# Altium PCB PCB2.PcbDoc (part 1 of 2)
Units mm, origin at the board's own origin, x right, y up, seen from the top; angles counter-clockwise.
Board outline 165.1 x 160.02 mm, 2 copper layers (Top Layer, Bottom Layer); 328 components, 756 nets, 2625 pads, 0 vias.
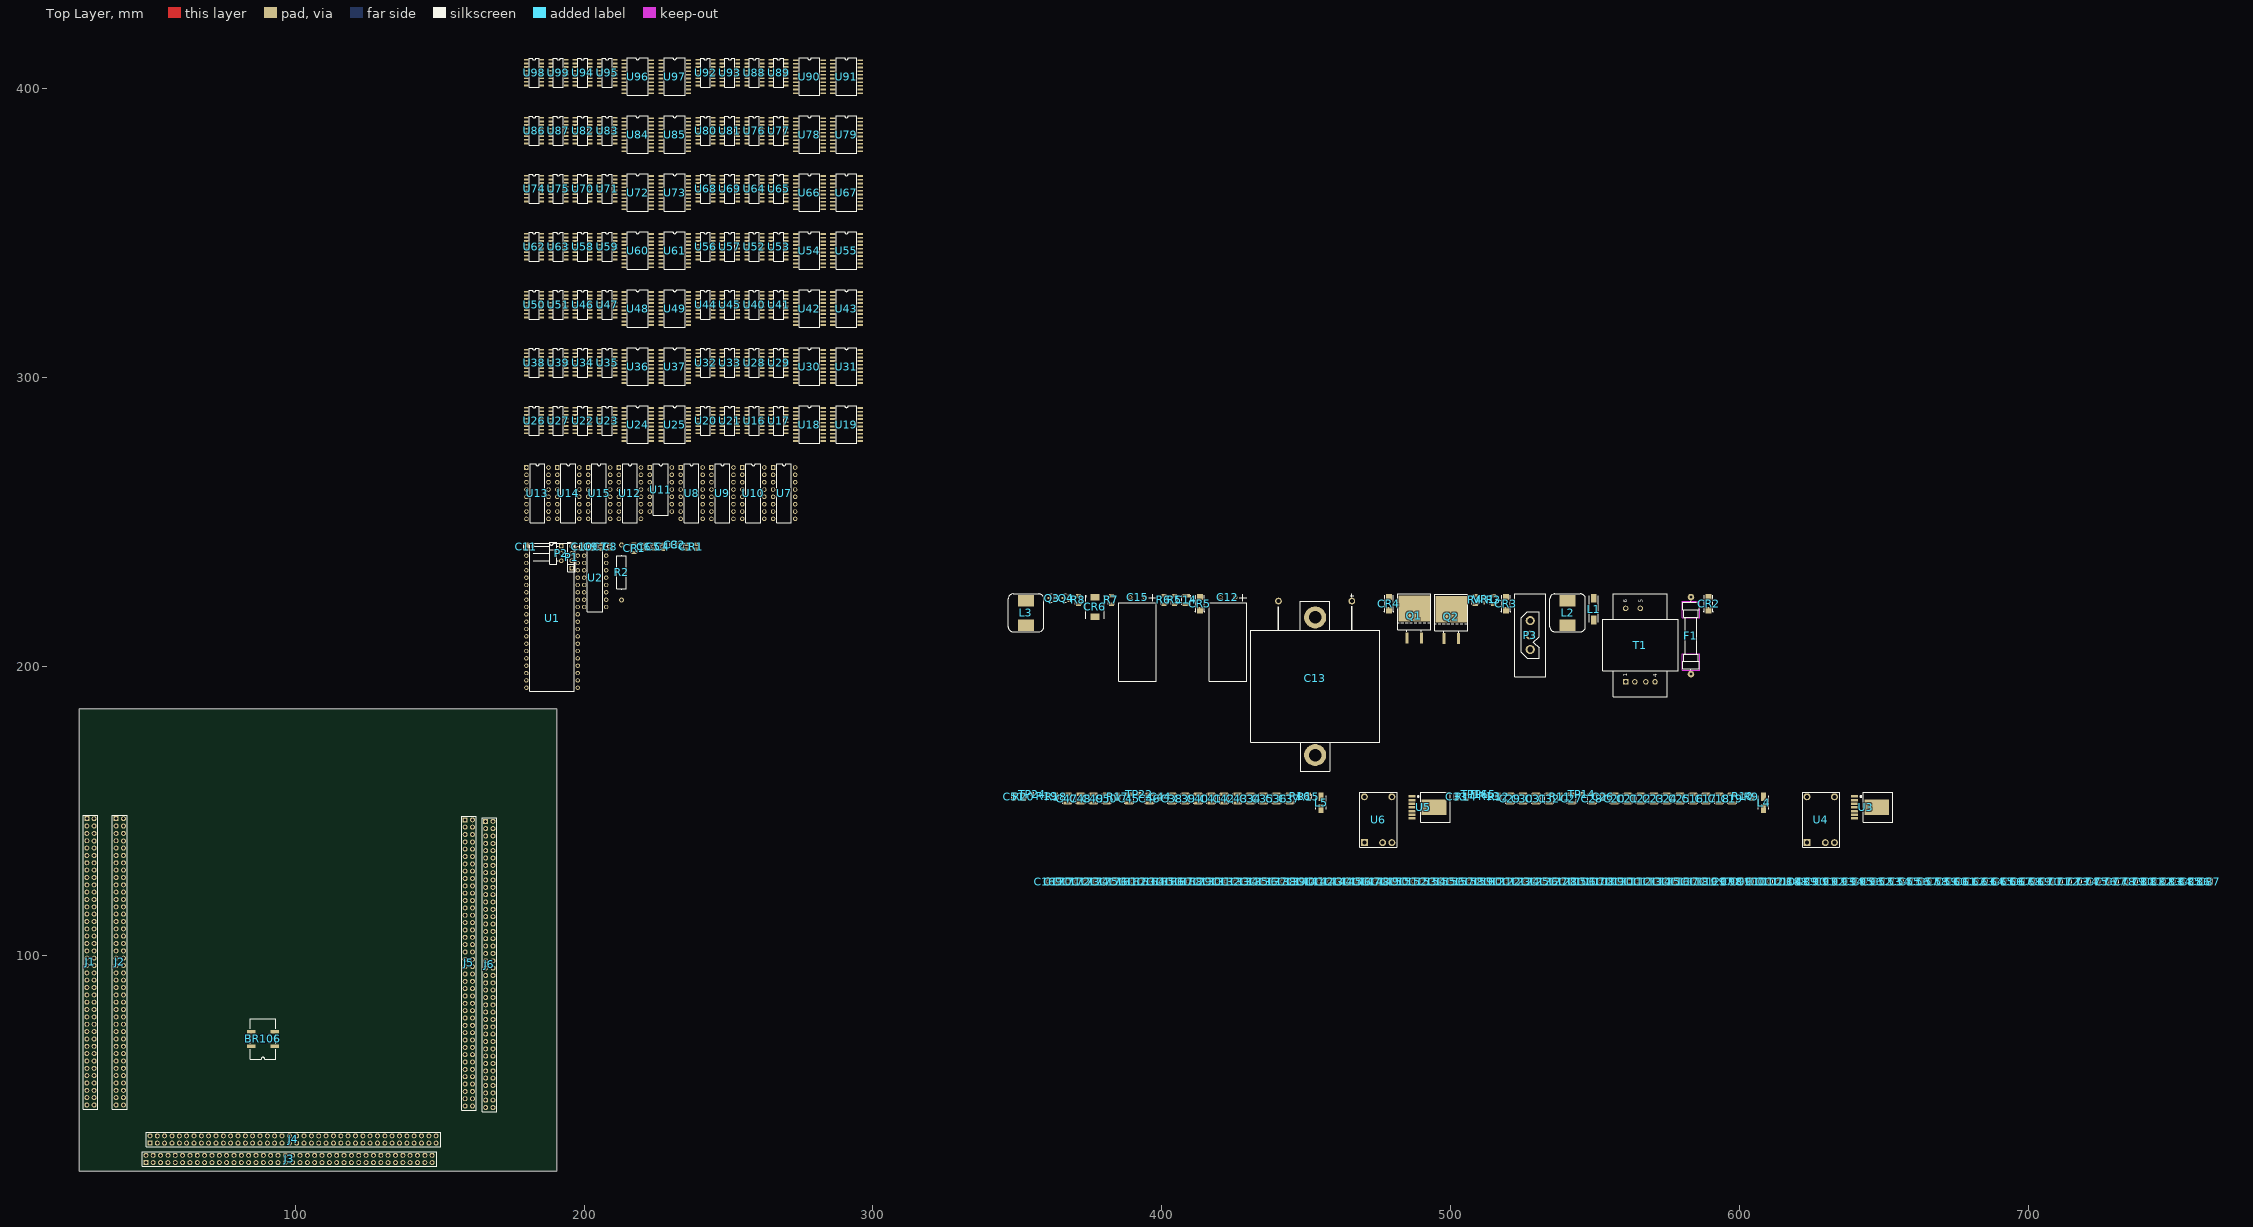
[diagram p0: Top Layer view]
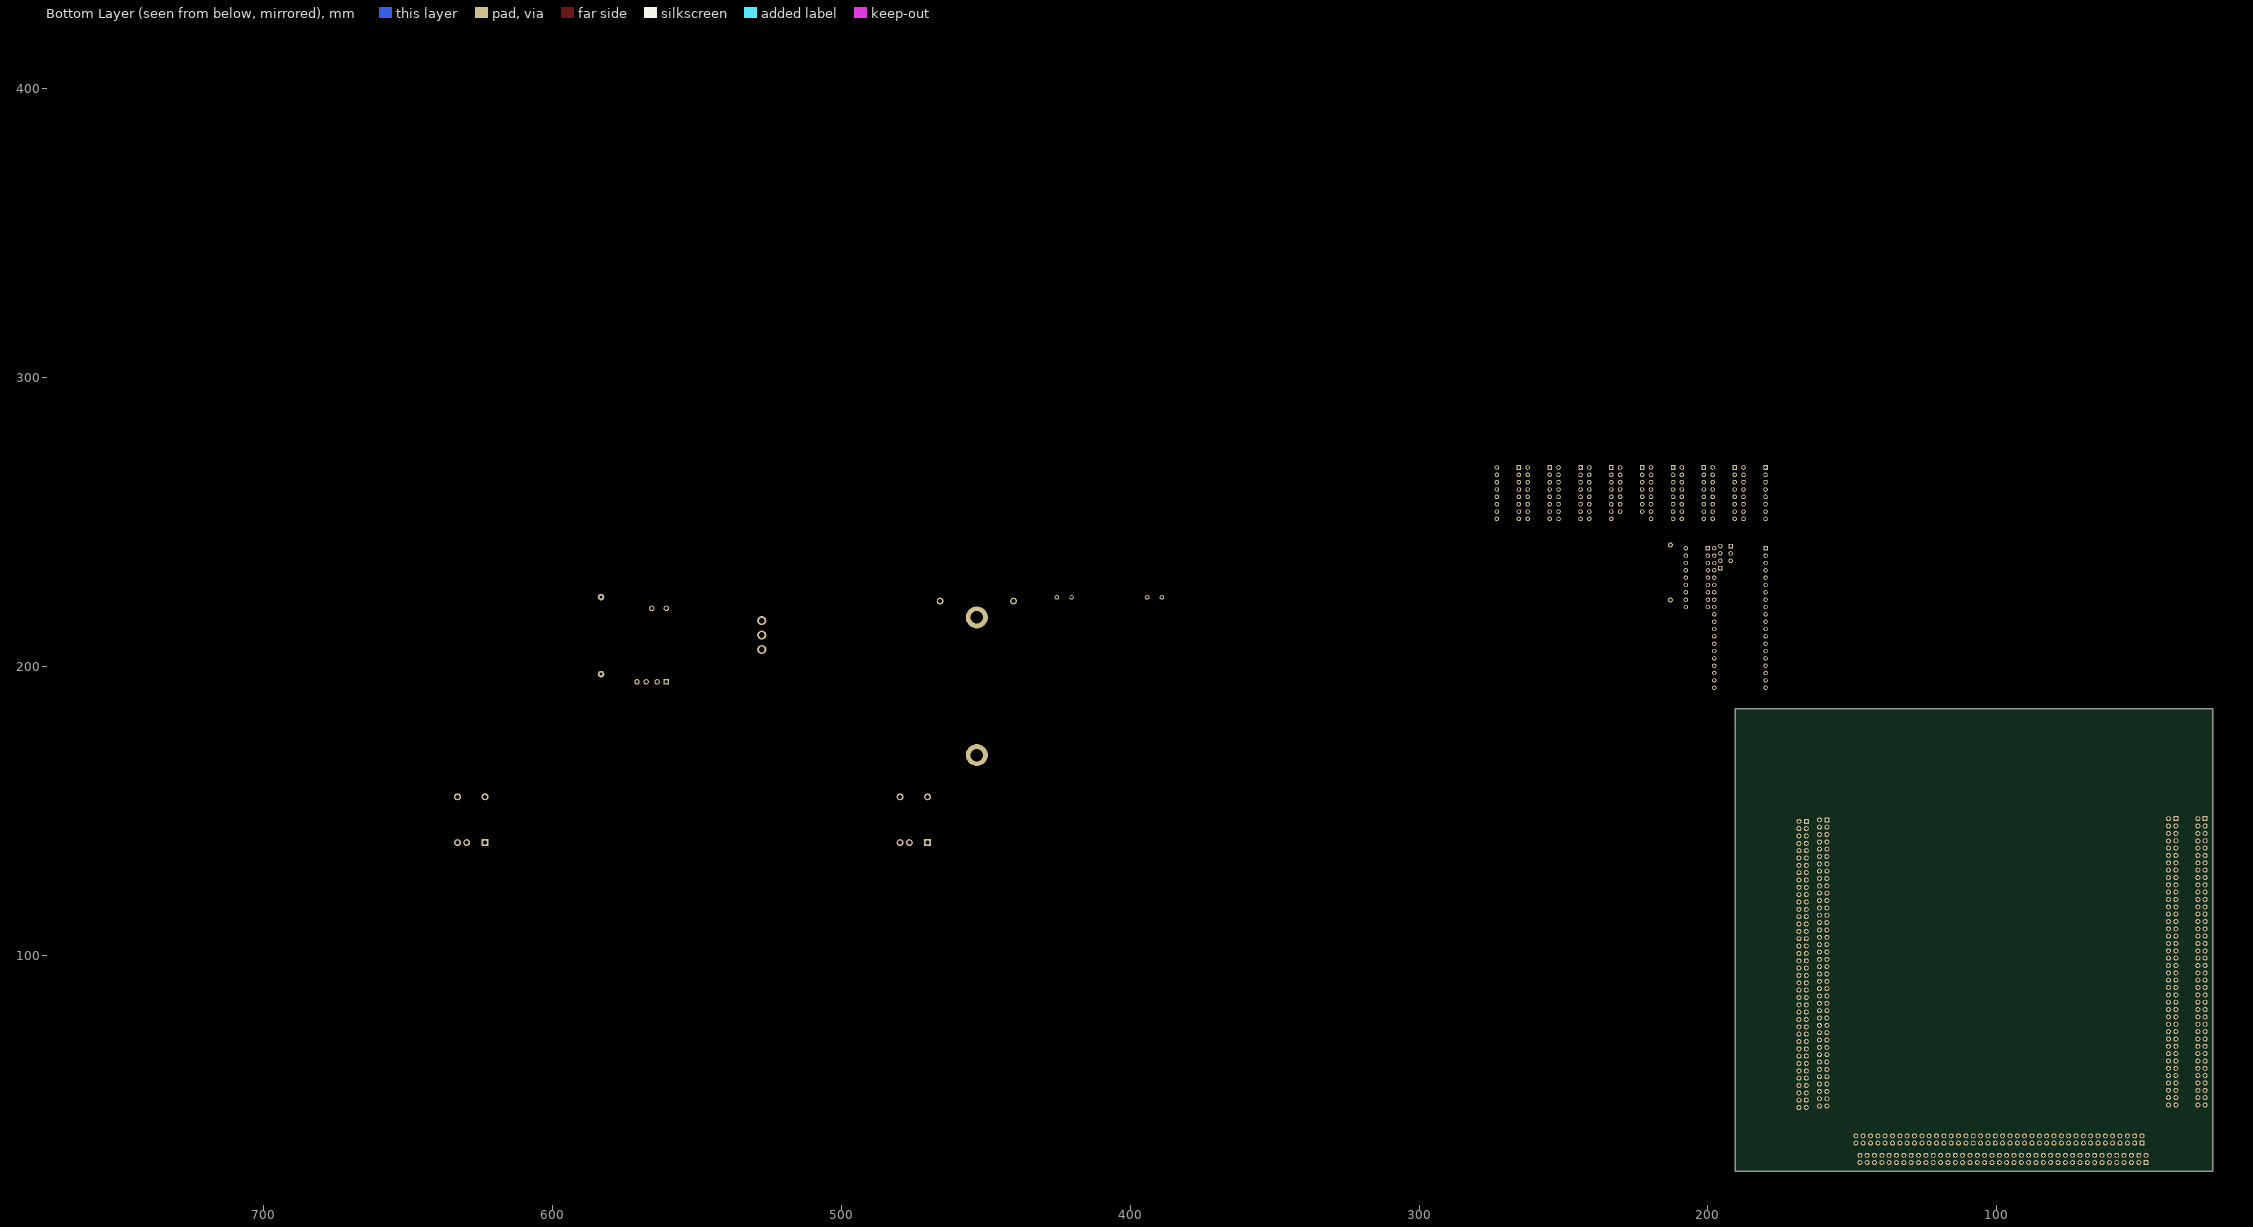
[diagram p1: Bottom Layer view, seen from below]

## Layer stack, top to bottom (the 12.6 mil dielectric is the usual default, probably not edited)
Top Layer: signal copper 0.0356
Dielectric: dielectric 0.32, FR-4, Dk 4.8
Bottom Layer: signal copper 0.0356

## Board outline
25.4,25.4 25.4,185.42 190.5,185.42 190.5,25.4

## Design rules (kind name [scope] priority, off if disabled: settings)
Clearance [All] p1: gap=0.254
PolygonConnect [All] p1: connectstyle=Relief reliefconductorwidth=0.254 reliefentries=4 polygonreliefangle="90 Angle" airgapwidth=0.254
RoomDefinition Latch7 [InComponentClass('Latch7')] p1: confinementstyle=ConfineIn formatcopy=TRUE lockcomponents=FALSE outline 178.943,397.383 296.799,397.383 296.799,410.845 178.943,410.845
RoomDefinition Latch6 [InComponentClass('Latch6')] p2: confinementstyle=ConfineIn formatcopy=TRUE lockcomponents=FALSE outline 178.943,377.317 296.799,377.317 296.799,390.779 178.943,390.779
RoomDefinition Latch5 [InComponentClass('Latch5')] p3: confinementstyle=ConfineIn formatcopy=TRUE lockcomponents=FALSE outline 178.943,357.251 296.799,357.251 296.799,370.713 178.943,370.713
RoomDefinition Latch4 [InComponentClass('Latch4')] p4: confinementstyle=ConfineIn formatcopy=TRUE lockcomponents=FALSE outline 178.943,337.185 296.799,337.185 296.799,350.647 178.943,350.647
RoomDefinition Latch3 [InComponentClass('Latch3')] p5: confinementstyle=ConfineIn formatcopy=TRUE lockcomponents=FALSE outline 178.943,317.119 296.799,317.119 296.799,330.581 178.943,330.581
RoomDefinition Latch2 [InComponentClass('Latch2')] p6: confinementstyle=ConfineIn formatcopy=TRUE lockcomponents=FALSE outline 178.943,297.053 296.799,297.053 296.799,310.515 178.943,310.515
RoomDefinition Latch1 [InComponentClass('Latch1')] p7: confinementstyle=ConfineIn formatcopy=TRUE lockcomponents=FALSE outline 178.943,276.987 296.799,276.987 296.799,290.449 178.943,290.449
RoomDefinition Decoder [InComponentClass('Decoder')] p8: confinementstyle=ConfineIn formatcopy=TRUE lockcomponents=FALSE outline 179.07,249.555 274.066,249.555 274.066,270.383 179.07,270.383
RoomDefinition Controller [InComponentClass('Controller')] p9: confinementstyle=ConfineIn formatcopy=TRUE lockcomponents=FALSE outline 178.943,221.869 239.903,221.869 239.903,243.205 178.943,243.205
RoomDefinition Connector [InComponentClass('Connector')] p10: confinementstyle=ConfineIn formatcopy=TRUE lockcomponents=FALSE outline 178.943,118.237 217.297,118.237 217.297,220.599 178.943,220.599
RoomDefinition ByPass [InComponentClass('ByPass')] p11: confinementstyle=ConfineIn formatcopy=TRUE lockcomponents=FALSE outline 359.664,123.814 763.778,123.814 763.778,127.37 359.664,127.37
RoomDefinition "28 PowerSupply" [InComponentClass('28 PowerSupply')] p12: confinementstyle=ConfineIn formatcopy=TRUE lockcomponents=FALSE outline 346.456,163.449 591.058,163.449 591.058,225.425 346.456,225.425
RoomDefinition "15 and 5 Volts" [InComponentClass('15 and 5 Volts')] p13: confinementstyle=ConfineIn formatcopy=TRUE lockcomponents=FALSE outline 347.726,137.263 653.161,137.263 653.161,156.694 347.726,156.694
RoutingVias [All] p1: holewidth=0.711 width=1.27 viastyle="Through Hole" minholewidth=0.711 minwidth=1.27 maxholewidth=0.711 maxwidth=1.27
SilkscreenOverComponentPads [All] p1: minsilkscreentomaskgap=0.254
SolderMaskExpansion [All] p1: expansion=0.102
Width [All] p1: maxlimit=0.254 minlimit=0.254 preferedwidth=0.254
27 further rules are at their usual default settings.

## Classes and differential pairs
net class Power1: NetCR2_1 NetCR4_2
net class D[0..7]: D0 D1 D2 D3 D4 D5 D6 D7
component class Latch7: U88 U89 U90 U91 U92 U93 U94 U95 U96 U97 U98 U99
component class Latch6: U76 U77 U78 U79 U80 U81 U82 U83 U84 U85 U86 U87
component class Latch5: U64 U65 U66 U67 U68 U69 U70 U71 U72 U73 U74 U75
component class Latch4: U52 U53 U54 U55 U56 U57 U58 U59 U60 U61 U62 U63
component class Latch3: U40 U41 U42 U43 U44 U45 U46 U47 U48 U49 U50 U51
component class Latch2: U28 U29 U30 U31 U32 U33 U34 U35 U36 U37 U38 U39
component class Latch1: U16 U17 U18 U19 U20 U21 U22 U23 U24 U25 U26 U27
component class Decoder: U7 U8 U9 U10 U11 U12 U13 U14 U15
component class Controller: C1 C2 C3 C4 C5 C6 C7 C8 C9 C10 C11 CR1 P1 P2 R1 R2 U1 U2 Y1
component class Connector: J1 J2 J3 J4 J5 J6
component class ByPass: C52 C53 C54 C55 C56 C57 C58 C59 C60 C61 C62 C63 C64 C65 C66 C67 C68 C69 C70 C71 C72 C73 C74 C75 C76 C77 C78 C79 C80 C81 C82 C83 C84 C85 C86 C87 C88 C89 C90 C91 C92 C93 C94 C95 C96 C97 C98 C99 C100 C101 C102 C103 C104 C105 C106 C107 C108 C109 C110 C111 C112 C113 C114 C115 C116 C117 C118 C119 C120 C121 C122 C123 C124 C125 C126 C127 C128 C129 C130 C131 C132 C133 C134 C135 C136 C137 C138 C139 C140 C141 C142 C143 C144 C145 C146 C147 C148 C149 C150 C151 C152 C153 C154 C155 C156 C157 C158 C159 C160 C161 C162 C163 C164 C165 C166 C167 C168 C169 C170 C171 C172 C173 C174 C175 C176
component class "28 PowerSupply": C12 C13 C14 C15 CR2 CR3 CR4 CR5 CR6 F1 L1 L2 L3 P3 Q1 Q2 Q3 Q4 R3 R4 R5 R6 R7 R8 T1 TP1 TP2 TP3 TP4 TP5 TP6 TP7 TP8 VR1 VR2 VR3
component class "15 and 5 Volts": C16 C17 C18 C19 C20 C21 C22 C23 C24 C25 C26 C27 C28 C29 C30 C31 C32 C33 C34 C35 C36 C37 C38 C39 C40 C41 C42 C43 C44 C45 C46 C47 C48 C49 C50 C51 L4 L5 R9 R10 R11 R12 R13 R14 R15 R16 R17 R18 R19 R20 TP14 TP15 TP16 TP22 TP24 U3 U4 U5 U6

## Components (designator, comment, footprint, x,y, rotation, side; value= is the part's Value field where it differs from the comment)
BR106 "Comment" XTAL1/N 88.9,71.12 r180 top
C1 "104-50V-10CX0805" 0805/1.3/N 235.458,241.427 r90 top
C2 "22P-25V-10NX0402" 0402/0.6/N 232.664,242.062 r90 top
C3 "22P-25V-10NX0402" 0402/0.6/N 230.124,242.062 r90 top
C4 "474-50V-10CX0805" 0805/1.4/N 227.33,241.427 r90 top
C5 "104-50V-10CX0805" 0805/1.3/N 224.155,241.427 r90 top
C6 "104-50V-10CX0805" 0805/1.3/N 220.853,241.427 r90 top
C7 "104-50V-10CX0805" 0805/1.3/N 205.867,241.427 r90 top
C8 "104-50V-10CX0805" 0805/1.3/N 209.042,241.427 r90 top
C9 "104-50V-10CX0805" 0805/1.3/N 202.565,241.427 r90 top
C10 "104-50V-10CX0805" 0805/1.3/N 199.39,241.427 r90 top
C11 "104-50V-10CX0805" 0805/1.3/N 180.086,241.427 r90 top
C12 "477-50V-20AV" RH+.2/.512/1 425.323,223.901 r0 top
C13 "MLPCAPSHORT" CAP_MLP222M063EK0A 440.309,222.631 r90 top
C14 "105-101-10CX1210" 1210/2.8/N 408.432,223.012 r90 top
C15 "477-50V-20AV" RH+.2/.512/1 394.081,223.901 r0 top
C16 "475-50V-10CX1210" 1210/2.8/N 583.819,154.281 r90 top
C17 "475-50V-10CX1210" 1210/2.8/N 588.264,154.281 r90 top
C18 "475-50V-10CX1210" 1210/2.8/N 592.836,154.281 r90 top
C19 "475-50V-10CX1210" 1210/2.8/N 597.281,154.281 r90 top
C20 "226-25V-10CX1210" 1210/2.8/N 556.641,154.281 r90 top
C21 "226-25V-10CX1210" 1210/2.8/N 561.213,154.281 r90 top
C22 "226-25V-10CX1210" 1210/2.8/N 565.658,154.281 r90 top
C23 "226-25V-10CX1210" 1210/2.8/N 570.23,154.281 r90 top
C24 "226-25V-10CX1210" 1210/2.8/N 574.675,154.281 r90 top
C25 "226-25V-10CX1210" 1210/2.8/N 579.247,154.281 r90 top
C26 "333-50V-10CX0805" 0805/1.3/N 552.704,154.916 r90 top
C27 "475-50V-10CX1210" 1210/2.8/N 541.782,154.281 r90 top
C28 "475-50V-10CX1210" 1210/2.8/N 548.894,154.281 r90 top
C29 "226-25V-10CX1210" 1210/2.8/N 520.446,154.281 r90 top
C30 "226-25V-10CX1210" 1210/2.8/N 524.891,154.281 r90 top
C31 "226-25V-10CX1210" 1210/2.8/N 529.463,154.281 r90 top
C32 "226-25V-10CX1210" 1210/2.8/N 534.035,154.281 r90 top
C33 "472-101-10CX0805" 0805/1.3/N 502.031,154.916 r90 top
C34 "475-50V-10CX1210" 1210/2.8/N 430.657,154.281 r90 top
C35 "475-50V-10CX1210" 1210/2.8/N 435.102,154.281 r90 top
C36 "475-50V-10CX1210" 1210/2.8/N 439.674,154.281 r90 top
C37 "475-50V-10CX1210" 1210/2.8/N 444.246,154.281 r90 top
C38 "226-25V-10CX1210" 1210/2.8/N 403.479,154.281 r90 top
C39 "226-25V-10CX1210" 1210/2.8/N 408.051,154.281 r90 top
C40 "226-25V-10CX1210" 1210/2.8/N 412.496,154.281 r90 top
C41 "226-25V-10CX1210" 1210/2.8/N 417.068,154.281 r90 top
C42 "226-25V-10CX1210" 1210/2.8/N 421.513,154.281 r90 top
C43 "226-25V-10CX1210" 1210/2.8/N 426.085,154.281 r90 top
C44 "333-50V-10CX0805" 0805/1.3/N 399.542,154.916 r90 top
C45 "475-50V-10CX1210" 1210/2.8/N 388.62,154.281 r90 top
C46 "475-50V-10CX1210" 1210/2.8/N 395.732,154.281 r90 top
C47 "226-25V-10CX1210" 1210/2.8/N 367.284,154.281 r90 top
C48 "226-25V-10CX1210" 1210/2.8/N 371.856,154.281 r90 top
C49 "226-25V-10CX1210" 1210/2.8/N 376.301,154.281 r90 top
C50 "226-25V-10CX1210" 1210/2.8/N 380.873,154.281 r90 top
C51 "472-101-10CX0805" 0805/1.3/N 348.869,154.916 r90 top
C52 "104-50V-10CX0805" 0805/1.3/N 649.224,125.592 r90 top
C53 "104-50V-10CX0805" 0805/1.3/N 652.399,125.592 r90 top
C54 "104-50V-10CX0805" 0805/1.3/N 655.701,125.592 r90 top
C55 "104-50V-10CX0805" 0805/1.3/N 658.876,125.592 r90 top
C56 "104-50V-10CX0805" 0805/1.3/N 662.178,125.592 r90 top
C57 "104-50V-10CX0805" 0805/1.3/N 665.353,125.592 r90 top
C58 "104-50V-10CX0805" 0805/1.3/N 668.655,125.592 r90 top
C59 "104-50V-10CX0805" 0805/1.3/N 671.83,125.592 r90 top
C60 "104-50V-10CX0805" 0805/1.3/N 675.132,125.592 r90 top
C61 "104-50V-10CX0805" 0805/1.3/N 678.307,125.592 r90 top
C62 "104-50V-10CX0805" 0805/1.3/N 681.609,125.592 r90 top
C63 "104-50V-10CX0805" 0805/1.3/N 684.784,125.592 r90 top
C64 "104-50V-10CX0805" 0805/1.3/N 688.086,125.592 r90 top
C65 "104-50V-10CX0805" 0805/1.3/N 691.261,125.592 r90 top
C66 "104-50V-10CX0805" 0805/1.3/N 694.563,125.592 r90 top
C67 "104-50V-10CX0805" 0805/1.3/N 697.738,125.592 r90 top
C68 "104-50V-10CX0805" 0805/1.3/N 701.04,125.592 r90 top
C69 "104-50V-10CX0805" 0805/1.3/N 704.342,125.592 r90 top
C70 "104-50V-10CX0805" 0805/1.3/N 707.517,125.592 r90 top
C71 "104-50V-10CX0805" 0805/1.3/N 710.819,125.592 r90 top
C72 "104-50V-10CX0805" 0805/1.3/N 713.994,125.592 r90 top
C73 "104-50V-10CX0805" 0805/1.3/N 717.296,125.592 r90 top
C74 "104-50V-10CX0805" 0805/1.3/N 720.471,125.592 r90 top
C75 "104-50V-10CX0805" 0805/1.3/N 723.773,125.592 r90 top
C76 "104-50V-10CX0805" 0805/1.3/N 726.948,125.592 r90 top
C77 "104-50V-10CX0805" 0805/1.3/N 730.25,125.592 r90 top
C78 "104-50V-10CX0805" 0805/1.3/N 733.425,125.592 r90 top
C79 "104-50V-10CX0805" 0805/1.3/N 736.727,125.592 r90 top
C80 "104-50V-10CX0805" 0805/1.3/N 739.902,125.592 r90 top
C81 "104-50V-10CX0805" 0805/1.3/N 743.204,125.592 r90 top
C82 "104-50V-10CX0805" 0805/1.3/N 746.379,125.592 r90 top
C83 "104-50V-10CX0805" 0805/1.3/N 749.681,125.592 r90 top
C84 "104-50V-10CX0805" 0805/1.3/N 752.856,125.592 r90 top
C85 "104-50V-10CX0805" 0805/1.3/N 756.158,125.592 r90 top
C86 "104-50V-10CX0805" 0805/1.3/N 759.333,125.592 r90 top
C87 "104-50V-10CX0805" 0805/1.3/N 762.635,125.592 r90 top
C88 "104-50V-10CX0805" 0805/1.3/N 620.014,125.592 r90 top
C89 "104-50V-10CX0805" 0805/1.3/N 623.316,125.592 r90 top
C90 "104-50V-10CX0805" 0805/1.3/N 626.491,125.592 r90 top
C91 "104-50V-10CX0805" 0805/1.3/N 629.793,125.592 r90 top
C92 "104-50V-10CX0805" 0805/1.3/N 632.968,125.592 r90 top
C93 "104-50V-10CX0805" 0805/1.3/N 636.27,125.592 r90 top
C94 "104-50V-10CX0805" 0805/1.3/N 639.445,125.592 r90 top
C95 "104-50V-10CX0805" 0805/1.3/N 642.747,125.592 r90 top
C96 "104-50V-10CX0805" 0805/1.3/N 645.922,125.592 r90 top
C97 "104-50V-10CX0805" 0805/1.3/N 594.106,125.592 r90 top
C98 "104-50V-10CX0805" 0805/1.3/N 597.408,125.592 r90 top
C99 "104-50V-10CX0805" 0805/1.3/N 600.583,125.592 r90 top
C100 "104-50V-10CX0805" 0805/1.3/N 603.885,125.592 r90 top
C101 "104-50V-10CX0805" 0805/1.3/N 607.06,125.592 r90 top
C102 "104-50V-10CX0805" 0805/1.3/N 610.362,125.592 r90 top
C103 "104-50V-10CX0805" 0805/1.3/N 613.537,125.592 r90 top
C104 "104-50V-10CX0805" 0805/1.3/N 616.839,125.592 r90 top
C105 "104-50V-10CX0805" 0805/1.3/N 542.29,125.592 r90 top
C106 "104-50V-10CX0805" 0805/1.3/N 545.465,125.592 r90 top
C107 "104-50V-10CX0805" 0805/1.3/N 548.767,125.592 r90 top
C108 "104-50V-10CX0805" 0805/1.3/N 551.942,125.592 r90 top
C109 "104-50V-10CX0805" 0805/1.3/N 555.244,125.592 r90 top
C110 "104-50V-10CX0805" 0805/1.3/N 558.419,125.592 r90 top
C111 "104-50V-10CX0805" 0805/1.3/N 561.721,125.592 r90 top
C112 "104-50V-10CX0805" 0805/1.3/N 564.896,125.592 r90 top
C113 "104-50V-10CX0805" 0805/1.3/N 568.198,125.592 r90 top
C114 "104-50V-10CX0805" 0805/1.3/N 571.5,125.592 r90 top
C115 "104-50V-10CX0805" 0805/1.3/N 574.675,125.592 r90 top
C116 "104-50V-10CX0805" 0805/1.3/N 577.977,125.592 r90 top
C117 "104-50V-10CX0805" 0805/1.3/N 581.152,125.592 r90 top
C118 "104-50V-10CX0805" 0805/1.3/N 584.454,125.592 r90 top
C119 "104-50V-10CX0805" 0805/1.3/N 587.629,125.592 r90 top
C120 "104-50V-10CX0805" 0805/1.3/N 590.931,125.592 r90 top
C121 "104-50V-10CX0805" 0805/1.3/N 516.382,125.592 r90 top
C122 "104-50V-10CX0805" 0805/1.3/N 519.557,125.592 r90 top
C123 "104-50V-10CX0805" 0805/1.3/N 522.859,125.592 r90 top
C124 "104-50V-10CX0805" 0805/1.3/N 526.034,125.592 r90 top
C125 "104-50V-10CX0805" 0805/1.3/N 529.336,125.592 r90 top
C126 "104-50V-10CX0805" 0805/1.3/N 532.511,125.592 r90 top
C127 "104-50V-10CX0805" 0805/1.3/N 535.813,125.592 r90 top
C128 "104-50V-10CX0805" 0805/1.3/N 538.988,125.592 r90 top
C129 "104-50V-10CX0805" 0805/1.3/N 412.623,125.592 r90 top
C130 "104-50V-10CX0805" 0805/1.3/N 415.925,125.592 r90 top
C131 "104-50V-10CX0805" 0805/1.3/N 419.1,125.592 r90 top
C132 "104-50V-10CX0805" 0805/1.3/N 422.402,125.592 r90 top
C133 "104-50V-10CX0805" 0805/1.3/N 425.577,125.592 r90 top
C134 "104-50V-10CX0805" 0805/1.3/N 428.879,125.592 r90 top
C135 "104-50V-10CX0805" 0805/1.3/N 432.181,125.592 r90 top
C136 "104-50V-10CX0805" 0805/1.3/N 435.356,125.592 r90 top
C137 "104-50V-10CX0805" 0805/1.3/N 438.658,125.592 r90 top
C138 "104-50V-10CX0805" 0805/1.3/N 441.833,125.592 r90 top
C139 "104-50V-10CX0805" 0805/1.3/N 445.135,125.592 r90 top
C140 "104-50V-10CX0805" 0805/1.3/N 448.31,125.592 r90 top
C141 "104-50V-10CX0805" 0805/1.3/N 451.612,125.592 r90 top
C142 "104-50V-10CX0805" 0805/1.3/N 454.787,125.592 r90 top
C143 "104-50V-10CX0805" 0805/1.3/N 458.089,125.592 r90 top
C144 "104-50V-10CX0805" 0805/1.3/N 461.264,125.592 r90 top
C145 "104-50V-10CX0805" 0805/1.3/N 464.566,125.592 r90 top
C146 "104-50V-10CX0805" 0805/1.3/N 467.741,125.592 r90 top
C147 "104-50V-10CX0805" 0805/1.3/N 471.043,125.592 r90 top
C148 "104-50V-10CX0805" 0805/1.3/N 474.218,125.592 r90 top
C149 "104-50V-10CX0805" 0805/1.3/N 477.52,125.592 r90 top
C150 "104-50V-10CX0805" 0805/1.3/N 480.695,125.592 r90 top
C151 "104-50V-10CX0805" 0805/1.3/N 483.997,125.592 r90 top
C152 "104-50V-10CX0805" 0805/1.3/N 487.172,125.592 r90 top
C153 "104-50V-10CX0805" 0805/1.3/N 490.474,125.592 r90 top
C154 "104-50V-10CX0805" 0805/1.3/N 493.649,125.592 r90 top
C155 "104-50V-10CX0805" 0805/1.3/N 496.951,125.592 r90 top
C156 "104-50V-10CX0805" 0805/1.3/N 500.126,125.592 r90 top
C157 "104-50V-10CX0805" 0805/1.3/N 503.428,125.592 r90 top
C158 "104-50V-10CX0805" 0805/1.3/N 506.603,125.592 r90 top
C159 "104-50V-10CX0805" 0805/1.3/N 509.905,125.592 r90 top
C160 "104-50V-10CX0805" 0805/1.3/N 513.08,125.592 r90 top
C161 "104-50V-10CX0805" 0805/1.3/N 386.715,125.592 r90 top
C162 "104-50V-10CX0805" 0805/1.3/N 390.017,125.592 r90 top
C163 "104-50V-10CX0805" 0805/1.3/N 393.192,125.592 r90 top
C164 "104-50V-10CX0805" 0805/1.3/N 396.494,125.592 r90 top
C165 "104-50V-10CX0805" 0805/1.3/N 399.669,125.592 r90 top
C166 "104-50V-10CX0805" 0805/1.3/N 402.971,125.592 r90 top
C167 "104-50V-10CX0805" 0805/1.3/N 406.146,125.592 r90 top
C168 "104-50V-10CX0805" 0805/1.3/N 409.448,125.592 r90 top
C169 "104-50V-10CX0805" 0805/1.3/N 360.807,125.592 r90 top
C170 "104-50V-10CX0805" 0805/1.3/N 364.109,125.592 r90 top
C171 "104-50V-10CX0805" 0805/1.3/N 367.284,125.592 r90 top
C172 "104-50V-10CX0805" 0805/1.3/N 370.586,125.592 r90 top
C173 "104-50V-10CX0805" 0805/1.3/N 373.761,125.592 r90 top
C174 "104-50V-10CX0805" 0805/1.3/N 377.063,125.592 r90 top
C175 "104-50V-10CX0805" 0805/1.3/N 380.238,125.592 r90 top
C176 "104-50V-10CX0805" 0805/1.3/N 383.54,125.592 r90 top
CR1 "1206_LED" 1206D/K/NP 217.297,240.919 r90 top
CR2 "D200V_2I0__X" SMA/NP 589.153,221.742 r90 top
CR3 "D200V_2I0__X" SMA/NP 519.049,221.742 r90 top
CR4 "D200V_2I0__X" SMA/NP 478.536,221.742 r90 top
CR5 "D200V_2I0__X" SMA/NP 413.131,221.742 r90 top
CR6 "Z36V0U3W0KZX" DO-214AB+/NP 376.809,220.599 r90 top
F1 "FUSE_1.0A_500VAC" AX1.05/.228 583.057,197.358 r90 top
J1 "2X40 HDR" H2X40 27.94,147.32 r0 top
J2 "2X40 HDR" H2X40 38.1,147.32 r0 top
J3 "2X40 HDR" H2X40 48.387,28.321 r90 top
J4 "2X40 HDR" H2X40 49.784,35.052 r90 top
J5 "2X40 HDR" H2X40 158.877,146.939 r0 top
J6 "2X40 HDR" H2X40 165.989,146.431 r0 top
L1 "2743021447_X" SM-118/295 549.402,219.837 r90 top
L2 "MSS1260" IND_MSS1260 540.385,218.567 r0 top
L3 "MSS1260" IND_MSS1260 352.933,218.567 r0 top
L4 "2773019447_X" SM-118/157 608.203,152.884 r90 top
L5 "2773019447_X" SM-118/157 455.041,152.884 r90 top
P1 "4P ST HDR 100" SIP4 195.707,234.061 r90 top
P2 "3P RA HDR 100" H3RA100 192.151,241.681 r90 top
P3 "1X3 ST HDR 5" H(JV01) 527.431,205.867 r90 top
Q1 "TMP100V_33IX" D2PAK4/N 487.299,216.281 r0 top
Q2 "TMP60V0_27IX" D2PAK4/N 500.126,216.027 r0 top
Q3 "FMMTA42" SOT-23/N 362.077,223.647 r90 top
Q4 "FMMTA42" SOT-23/N 366.903,223.647 r90 top
R1 "R10K00D1#0AX0805" 0805/N 238.76,241.427 r90 top
R2 "R56R00E1#0EW" AX.55/.125L 212.979,225.552 r90 top
R3 "R20K00D1#0BX1206" 1206/N 514.731,223.012 r90 top
R4 "R1206_499K" 1206/N 508.381,223.012 r90 top
R5 "R47K50D1#0BX1206" 1206/N 404.368,223.012 r90 top
R6 "R20K00D1#0BX1206" 1206/N 400.685,223.012 r90 top
R7 "R20K00D1#0BX1206" 1206/N 382.524,223.012 r90 top
R8 "R10K00D1#0BX1206" 1206/N 371.094,223.012 r90 top
R9 "R249K0D1#0AX0805" 0805/N 604.012,154.916 r90 top
R10 "R26K70D1#0GX0603" 0603/N 600.964,155.17 r90 top
R11 "R10K00D1#0AX0805" 0805/N 537.845,154.916 r90 top
R12 "R15K00D1#0AX0805" 0805/N 516.509,154.916 r90 top
R13 "R1K500Z5#0AX0603" 0603/N 513.461,155.17 r90 top
R14 "R1K000D1#0AX0805" 0805/N 505.333,154.916 r90 top
R15 "R249K0D1#0AX0805" 0805/N 450.85,154.916 r90 top
R16 "R26K70D1#0GX0603" 0603/N 447.802,155.17 r90 top
R17 "R10K00D1#0AX0805" 0805/N 384.683,154.916 r90 top
R18 "R15K00D1#0AX0805" 0805/N 363.347,154.916 r90 top
R19 "R1K500Z5#0AX0603" 0603/N 360.299,155.17 r90 top
R20 "R1K000D1#0AX0805" 0805/N 352.171,154.916 r90 top
T1 "B1460-BH-003" "XFMR (BH03)" 565.531,207.391 r90 top
TP14 "TP_SMT" TP_SMT 545.338,155.805 r90 top
TP15 "TP_SMT" TP_SMT 510.794,155.805 r90 top
TP16 "TP_SMT" TP_SMT 508.254,155.805 r90 top
TP22 "TP_SMT" TP_SMT 392.176,155.805 r90 top
TP24 "TP_SMT" TP_SMT 355.092,155.805 r90 top
U1 "PIC18LF4550-I/P" DIP40 180.049,240.905 r0 top
U2 "MAX3232CPE" DIP-18 203.85,230.747 r0 top
U3 "LMZ14203_X" TO-PMOD-7 647.319,151.233 r0 top
U4 "PTN78000HAH" R_PDSS_T5 623.189,139.041 r90 top
U5 "LMZ14203_X" TO-PMOD-7 494.157,151.233 r0 top
U6 "PTN78000HAH" R_PDSS_T5 470.027,139.041 r90 top
U7 "74AC138B" DIP16 265.43,268.859 r0 top
U8 "74AC138B" DIP16 233.426,268.859 r0 top
U9 "74AC138B" DIP16 244.094,268.859 r0 top
U10 "74AC138B" DIP16 254.762,268.859 r0 top
U11 "74ACT14" DIP14 222.758,268.859 r0 top
U12 "74AC138B" DIP16 212.09,268.859 r0 top
U13 "74AC138B" DIP16 180.086,268.859 r0 top
U14 "74AC138B" DIP16 190.754,268.859 r0 top
U15 "74AC138B" DIP16 201.422,268.859 r0 top
U16 "ADG439" SO-16/N 258.953,285.115 r0 top
U17 "ADG439" SO-16/N 267.335,285.115 r0 top
U18 "74ACT373_X" SOL-20/N 278.003,283.718 r0 top
U19 "74ACT373_X" SOL-20/N 290.83,283.718 r0 top
U20 "ADG439" SO-16/N 242.062,285.115 r0 top
U21 "ADG439" SO-16/N 250.444,285.115 r0 top
U22 "ADG439" SO-16/N 199.517,285.115 r0 top
U23 "ADG439" SO-16/N 208.026,285.115 r0 top
U24 "74ACT373_X" SOL-20/N 218.567,283.718 r0 top
U25 "74ACT373_X" SOL-20/N 231.394,283.718 r0 top
U26 "ADG439" SO-16/N 182.753,285.115 r0 top
U27 "ADG439" SO-16/N 191.135,285.115 r0 top
U28 "ADG442" SO-16/N 258.953,305.181 r0 top
U29 "ADG442" SO-16/N 267.335,305.181 r0 top
U30 "74ACT373_X" SOL-20/N 278.003,303.784 r0 top
U31 "74ACT373_X" SOL-20/N 290.83,303.784 r0 top
U32 "ADG442" SO-16/N 242.062,305.181 r0 top
U33 "ADG442" SO-16/N 250.444,305.181 r0 top
U34 "ADG442" SO-16/N 199.517,305.181 r0 top
U35 "ADG442" SO-16/N 208.026,305.181 r0 top
U36 "74ACT373_X" SOL-20/N 218.567,303.784 r0 top
U37 "74ACT373_X" SOL-20/N 231.394,303.784 r0 top
U38 "ADG442" SO-16/N 182.753,305.181 r0 top
U39 "ADG442" SO-16/N 191.135,305.181 r0 top
U40 "ADG442" SO-16/N 258.953,325.247 r0 top
U41 "ADG442" SO-16/N 267.335,325.247 r0 top
U42 "74ACT373_X" SOL-20/N 278.003,323.85 r0 top
U43 "74ACT373_X" SOL-20/N 290.83,323.85 r0 top
U44 "ADG442" SO-16/N 242.062,325.247 r0 top
U45 "ADG442" SO-16/N 250.444,325.247 r0 top
U46 "ADG442" SO-16/N 199.517,325.247 r0 top
U47 "ADG442" SO-16/N 208.026,325.247 r0 top
U48 "74ACT373_X" SOL-20/N 218.567,323.85 r0 top
U49 "74ACT373_X" SOL-20/N 231.394,323.85 r0 top
U50 "ADG442" SO-16/N 182.753,325.247 r0 top
U51 "ADG442" SO-16/N 191.135,325.247 r0 top
U52 "ADG442" SO-16/N 258.953,345.313 r0 top
U53 "ADG442" SO-16/N 267.335,345.313 r0 top
U54 "74ACT373_X" SOL-20/N 278.003,343.916 r0 top
U55 "74ACT373_X" SOL-20/N 290.83,343.916 r0 top
U56 "ADG442" SO-16/N 242.062,345.313 r0 top
U57 "ADG442" SO-16/N 250.444,345.313 r0 top
U58 "ADG442" SO-16/N 199.517,345.313 r0 top
U59 "ADG442" SO-16/N 208.026,345.313 r0 top
U60 "74ACT373_X" SOL-20/N 218.567,343.916 r0 top
U61 "74ACT373_X" SOL-20/N 231.394,343.916 r0 top
U62 "ADG442" SO-16/N 182.753,345.313 r0 top
U63 "ADG442" SO-16/N 191.135,345.313 r0 top
U64 "ADG442" SO-16/N 258.953,365.379 r0 top
U65 "ADG442" SO-16/N 267.335,365.379 r0 top
U66 "74ACT373_X" SOL-20/N 278.003,363.982 r0 top
U67 "74ACT373_X" SOL-20/N 290.83,363.982 r0 top
U68 "ADG442" SO-16/N 242.062,365.379 r0 top
U69 "ADG442" SO-16/N 250.444,365.379 r0 top
U70 "ADG442" SO-16/N 199.517,365.379 r0 top
U71 "ADG442" SO-16/N 208.026,365.379 r0 top
U72 "74ACT373_X" SOL-20/N 218.567,363.982 r0 top
U73 "74ACT373_X" SOL-20/N 231.394,363.982 r0 top
U74 "ADG442" SO-16/N 182.753,365.379 r0 top
U75 "ADG442" SO-16/N 191.135,365.379 r0 top
U76 "ADG442" SO-16/N 258.953,385.445 r0 top
U77 "ADG442" SO-16/N 267.335,385.445 r0 top
U78 "74ACT373_X" SOL-20/N 278.003,384.048 r0 top
U79 "74ACT373_X" SOL-20/N 290.83,384.048 r0 top
U80 "ADG442" SO-16/N 242.062,385.445 r0 top
U81 "ADG442" SO-16/N 250.444,385.445 r0 top
U82 "ADG442" SO-16/N 199.517,385.445 r0 top
U83 "ADG442" SO-16/N 208.026,385.445 r0 top
U84 "74ACT373_X" SOL-20/N 218.567,384.048 r0 top
U85 "74ACT373_X" SOL-20/N 231.394,384.048 r0 top
U86 "ADG442" SO-16/N 182.753,385.445 r0 top
U87 "ADG442" SO-16/N 191.135,385.445 r0 top
U88 "ADG442" SO-16/N 258.953,405.511 r0 top
U89 "ADG442" SO-16/N 267.335,405.511 r0 top
U90 "74ACT373_X" SOL-20/N 278.003,404.114 r0 top
U91 "74ACT373_X" SOL-20/N 290.83,404.114 r0 top
U92 "ADG442" SO-16/N 242.062,405.511 r0 top
U93 "ADG442" SO-16/N 250.444,405.511 r0 top
U94 "ADG442" SO-16/N 199.517,405.511 r0 top
U95 "ADG442" SO-16/N 208.026,405.511 r0 top
U96 "74ACT373_X" SOL-20/N 218.567,404.114 r0 top
U97 "74ACT373_X" SOL-20/N 231.394,404.114 r0 top
U98 "ADG442" SO-16/N 182.753,405.511 r0 top
U99 "ADG442" SO-16/N 191.135,405.511 r0 top
VR1 "BZT52C" SOD323/NP 511.556,223.266 r90 top

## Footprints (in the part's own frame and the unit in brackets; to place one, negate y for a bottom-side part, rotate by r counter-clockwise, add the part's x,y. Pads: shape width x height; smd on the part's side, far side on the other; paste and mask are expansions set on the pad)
0402/0.6/N [mm] "Checked RSK 8/7/13"
  rect 0.62x0.62 smd: 1(-0.5,0) 2(0.5,0)
  silkscreen extent -0.51,-0.51 0.51,0.51, body extent -0.55,-0.29 0.55,0.31, height 0.58
0603/N [mm] "RESC1608X50N Checked RSK 8/7/13"
  rect 0.95x1 smd: 1(-0.8,0) 2(0.8,0)
  silkscreen extent -0.63,-0.7 0.64,0.7, body extent -0.95,-0.5 0.85,0.5, height 0.32
0805/1.3/N [mm] "CHKD GRL 8/27/13"
  rect 1.2x1.4 smd: 1(-0.9,0) 2(0.9,0)
  silkscreen extent -0.9,-0.91 0.9,0.91, body extent -1.13,-0.7 1.12,0.7, height 1.29
0805/1.4/N [mm] "CHKD GRL 8/27/13"
  rect 1.2x1.4 smd: 1(-0.9,0) 2(0.9,0)
  silkscreen extent -0.9,-0.91 0.9,0.91, body extent -1.13,-0.7 1.11,0.7, height 1.39
0805/N [mm] "RESC2013X70N updated 3D 3/26/12 Checked RSK 8/7/13"
  rect 1.2x1.4 smd: 1(-0.9,0) 2(0.9,0)
  silkscreen extent -0.9,-0.91 0.9,0.91, body extent -1.12,-0.7 1.13,0.7, height 0.7
1206/N [mm] "RESC3216N   Checked RSK 8/7/13"
  rect 1.3x1.8 smd: 1(-1.5,0) 2(1.5,0)
  silkscreen extent -1.5,-1.12 1.5,1.12, body extent -1.63,-0.86 1.82,0.86, height 0.76
1206D/K/NP [mm] "LEDC3216X110N GTN 9/22/06"
  rect 1.1x1.75 smd: 1(1.499,0) 2(-1.5,0)
  silkscreen extent -1.6,-1.25 1.6,1.25, body extent -1.64,-0.87 1.81,0.86, height 0.76
1210/2.8/N [mm] "1210N to 1210/2.8/N"
  rect 1.15x2.7 smd: 1(-1.5,0) 2(1.5,0)
  silkscreen extent -1.7,-1.55 1.7,1.55, body extent -1.71,-1.4 1.69,1.4, height 2.78
AX1.05/.228 [mil] "15A FUSE  GRL 2/22/08 - Added 3D 3/27/12"
  round 90 hole 42: 1(0,0) 2(1050,0)
  Top Layer keep-out lines w2: 55,120 55,-120 280,-120 280,120 55,120 ; 770,120 995,120 995,-120 770,-120 770,120
  silkscreen extent 55,-116 995,114, body extent -23,-114 1073,114, height 227
AX.55/.125L [mil] "Standard part formed with long leads"
  oval 68x64 hole 42: 1(-100,0) 2(650,0)
  silkscreen extent 40,-62 510,63
CAP_MLP222M063EK0A [mil] "RSK 8/7/13"
  round 92 hole 54: 1(0,-1000) 2(0,0)
  round 300 hole 169: 3(-2097.5,-500) 4(-222.5,-500)
  silkscreen extent -2320,-1380 100,380, body extent -1920,-1380 20,380, height 500
D2PAK4/N [mm] "TO-263AB 4 PINS Checked RSK 8/7/13"
  round 0.635 on Mech15: 0(-5.207,8.89) 0(5.207,8.89)
  rect 1.05x3.8 smd: 1(-2.54,-6.4) 3(2.54,-6.4)
  rect 10.8x9.05 smd: 4(0,3.8)
  silkscreen extent -5.71,-4.27 5.71,8.89, body extent -5.15,-7.9 5.52,7.98, height 4.83
DIP14 [mil]
  rect 62x62 hole 36: 1(0,0)
  round 62 hole 36: 2(0,-100) 3(0,-200) 4(0,-300) 5(0,-400) 6(0,-500) 7(0,-600) 8(300,-600) 9(300,-500) 10(300,-400) 11(300,-300) 12(300,-200) 13(300,-100) 14(300,0)
  silkscreen extent 50,-650 250,50
DIP16 [mil]
  rect 62x62 hole 36: 1(0,0)
  round 62 hole 36: 2(0,-100) 3(0,-200) 4(0,-300) 5(0,-400) 6(0,-500) 7(0,-600) 8(0,-700) 9(300,-700) 10(300,-600) 11(300,-500) 12(300,-400) 13(300,-300) 14(300,-200) 15(300,-100) 16(300,0)
  silkscreen extent 50,-750 250,50
DIP40 [mm] "DIP; 40"
  rect 1.5x1.5 hole 0.9: 1(0,0)
  round 1.5 hole 0.9: 2(0,-2.54) 3(0,-5.08) 4(0,-7.62) 5(0,-10.16) 6(0,-12.7) 7(0,-15.24) 8(0,-17.78) 9(0,-20.32) 10(0,-22.86) 11(0,-25.4) 12(0,-27.94) 13(0,-30.48) 14(0,-33.02) 15(0,-35.56) 16(0,-38.1) 17(0,-40.64) 18(0,-43.18) 19(0,-45.72) 20(0,-48.26) 21(17.78,0) 22(17.78,-2.54) 23(17.78,-5.08) 24(17.78,-7.62) 25(17.78,-10.16) 26(17.78,-12.7) 27(17.78,-15.24) 28(17.78,-17.78) 29(17.78,-20.32) 30(17.78,-22.86) 31(17.78,-25.4) 32(17.78,-27.94) 33(17.78,-30.48) 34(17.78,-33.02) 35(17.78,-35.56) 36(17.78,-38.1) 37(17.78,-40.64) 38(17.78,-43.18) 39(17.78,-45.72) 40(17.78,-48.26)
  silkscreen extent -0.12,-49.53 16.51,1.69
DIP-18 [mm] "DIP; 18 Leads; Row Spacing 7.62 mm; Pitch 2.54 mm"
  rect 1.5x1.5 hole 0.9: 1(-3.81,10.16)
  round 1.5 hole 0.9: 2(-3.81,7.62) 3(-3.81,5.08) 4(-3.81,2.54) 5(-3.81,0) 6(-3.81,-2.54) 7(-3.81,-5.08) 8(-3.81,-7.62) 9(-3.81,-10.16) 10(3.81,-10.16) 11(3.81,-7.62) 12(3.81,-5.08) 13(3.81,-2.54) 14(3.81,0) 15(3.81,2.54) 16(3.81,5.08) 17(3.81,7.62) 18(3.81,10.16)
  silkscreen extent -3.93,-11.85 2.65,11.85, body extent -3.6,-11.8 3.6,11.8, height 5.08
DO-214AB+/NP [mil] "DIOM7959X265N ( SMC)     GTN 9/25/06  Checked RSK 8/7/13"
  rect 87x125 smd: 1(135,0) 2(-135,0)
  silkscreen extent -157,-124 158,124, body extent -156,-116 156,116, height 91
H2X40 [mil]
  rect 68x68 hole 41: 1(0,0)
  round 68 hole 41: 2(100,0) 3(0,-100) 4(100,-100) 5(0,-200) 6(100,-200) 7(0,-300) 8(100,-303) 9(0,-400) 10(100,-400) 11(0,-500) 12(100,-500) 13(0,-600) 14(100,-600) 15(0,-700) 16(100,-700) 17(0,-800) 18(100,-800) 19(0,-900) 20(100,-900) 21(0,-1000) 22(100,-1000) 23(0,-1100) 24(100,-1100) 25(0,-1200) 26(100,-1200) 27(0,-1300) 28(100,-1300) 29(0,-1400) 30(100,-1400) 31(0,-1500) 32(100,-1500) 33(0,-1600) 34(100,-1600) 35(0,-1700) 36(100,-1700) 37(0,-1800) 38(100,-1800) 39(0,-1900) 40(100,-1900) 41(0,-2000) 42(100,-2000) 43(0,-2100) 44(100,-2100) 45(0,-2200) 46(100,-2200) 47(0,-2300) 48(100,-2300) 49(0,-2400) 50(100,-2400) 51(0,-2500) 52(100,-2500) 53(0,-2600) 54(100,-2600) 55(0,-2700) 56(100,-2700) 57(0,-2800) 58(100,-2800) 59(0,-2900) 60(100,-2900) 61(0,-3000) 62(100,-3000) 63(0,-3100) 64(100,-3100) 65(0,-3200) 66(100,-3200) 67(0,-3300) 68(100,-3300) 69(0,-3400) 70(100,-3400) 71(0,-3500) 72(100,-3500) 73(0,-3600) 74(100,-3600) 75(0,-3700) 76(100,-3700) 77(0,-3800) 78(100,-3800) 79(0,-3900) 80(100,-3900)
  silkscreen extent -50,-3960 150,50
H3RA100 [mil]
  rect 62x62 hole 36: 1(0,0)
  round 62 hole 36: 2(-100.79,0) 3(-200.79,0)
  silkscreen extent -251,40 49,380
H(JV01) [mm] "3P 30A ST PCB FEMALE"
  round 2.54 hole 3.1 unplated: 0(-6.15,0) 0(16.15,0)
  round 3.175 hole 2: 1(0,0) 2(5,0) 3(10,0)
  silkscreen extent -9.35,-5.33 19.35,5.33, body extent -9.27,-5.22 19.23,5.18, height 15.32
IND_MSS1260 [mm] "GRL 5/2/13"
  rect 5.5x4 smd: 1(0,4.25) 2(0,-4.25)
  silkscreen extent -6.15,-6.58 6.15,6.58, body extent -6.2,-6.15 6.1,6.15, height 6.2
R_PDSS_T5 [mil] "THRU-HOLE"
  rect 95x95 hole 55: 1(0,0)
  round 95 hole 55: 2(0,-250) 3(0,-375) 4(625,-375) 5(625,0)
  silkscreen extent -60,-440 686,60
RH+.2/.512/1 [mil] "Added 3D 3/27/12"
  round 62 hole 36: 1(0,0) 2(-200,0)
  silkscreen extent -355,-1140 155,45, body extent -355,-1144 155,12, height 511
SIP4 [mil]
  rect 62x62 hole 36: 1(0,0)
  round 62 hole 36: 2(100,0) 3(200,0) 4(300,0)
  silkscreen extent -50,-50 350,50, body extent -50,-50 350,50, height 15
SM-118/157 [mil] "GTN 5/4/07"
  rect 118x70 smd: 1(79,0) 2(-79,0)
  silkscreen extent -92,-70 92,70, body extent -98,-62 97,62, height 112
SM-118/295 [mil] "GTN 3/19/07  CHECKED GRL 5/10/13"
  rect 118x71 smd: 1(148,0) 2(-148,0)
  silkscreen extent -180,-60 180,60, body extent -180,-60 180,60, height 0
SMA/NP [mil] "SMA/N GTN 9/8/06"
  rect 85x85 smd: 1(-90.5,0) 2(90.5,0)
  silkscreen extent -112,-66 112,66, body extent -102,-52 102,51, height 96
SO-16/N [mm] "SO-16/N GTN 2/13/08 / 3D MODEL ADDED 5/8/12,RSK 8/12/13"
  rect 1.55x0.6 smd: 1(-2.7,4.445) 2(-2.7,3.175) 3(-2.7,1.905) 4(-2.7,0.635) 5(-2.7,-0.635) 6(-2.7,-1.905) 7(-2.7,-3.175) 8(-2.7,-4.445) 9(2.7,-4.445) 10(2.7,-3.175) 11(2.7,-1.905) 12(2.7,-0.635) 13(2.7,0.635) 14(2.7,1.905) 15(2.7,3.175) 16(2.7,4.445)
  silkscreen extent -1.7,-5.01 1.7,5.01, body extent -3.05,-5.08 2.95,5.12, height 1.7
SOD323/NP [mm] "SOD-323; 2 Leads; Body 2.3 x 1.4mm, (LxW) updated 3D 3/26/12"
  rect 1.35x0.508 smd: 1(1.2,0) 2(-1.2,0)
  silkscreen extent -0.85,-0.65 0.85,0.65, body extent -1.33,-0.66 1.27,0.69, height 1.1
SOL-20/N [mm] "SOL-20/N GTN 9/21/06"
  rect 1.85x0.6 smd: 1(-4.75,5.715) 2(-4.75,4.445) 3(-4.75,3.175) 4(-4.75,1.905) 5(-4.75,0.635) 6(-4.75,-0.635) 7(-4.75,-1.905) 8(-4.75,-3.175) 9(-4.75,-4.445) 10(-4.75,-5.715) 11(4.75,-5.715) 12(4.75,-4.445) 13(4.75,-3.175) 14(4.75,-1.905) 15(4.75,-0.635) 16(4.75,0.635) 17(4.75,1.905) 18(4.75,3.175) 19(4.75,4.445) 20(4.75,5.715)
  silkscreen extent -3.6,-6.5 3.6,6.5
SOT-23/N [mm] "SOT95P240-3N  GRL 4/22/13 ,RSK 8/7/13"
  rect 0.65x1.3 smd: 1(-0.95,-1) 2(0.95,-1) 3(0,1)
  silkscreen extent -1.47,-0.7 1.45,0.7, body extent -1.53,-1.19 1.47,1.31, height 1.12
TO-PMOD-7 [mm] "TO-PMOD-7, TZA07A 7 PIN PACKAGE WITH HEAT SINK PAD"
  rect 2.41x0.89 smd: 1(-7.63,3.81) 2(-7.63,2.54) 3(-7.63,1.27) 4(-7.63,0) 5(-7.63,-1.27) 6(-7.63,-2.54) 7(-7.63,-3.81)
  rect 8.54x5.35 smd: 8(0,0)
  silkscreen extent -5.78,-5.2 5.57,5.2, body extent -4.58,-5.29 5.57,5.25, height 4.57
TP_SMT [mil] "0.035 DIA., OCTAGONAL, SMT - fixed Paste 10/11/12"
  oct 35x35 smd paste-50: 1(0,0)
  silkscreen extent -24,-24 24,24
"XFMR (BH03)" [mil] "GRL 5/13/13"
  rect 75x75 hole 47: 1(-500,200)
  round 75 hole 47: 2(-500,75) 3(-500,-75) 4(-500,-200) 5(500,0) 6(500,200)
  silkscreen extent -700,-515 700,515
XTAL1/N [mm] "XTAL1/N GTN 9/19/06"
  rect 2.9x1.15 smd: 1(-4.05,2.54) 2(-4.05,-2.54) 3(4.05,-2.54) 4(4.05,2.54)
  silkscreen extent -4.47,-7 4.47,7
